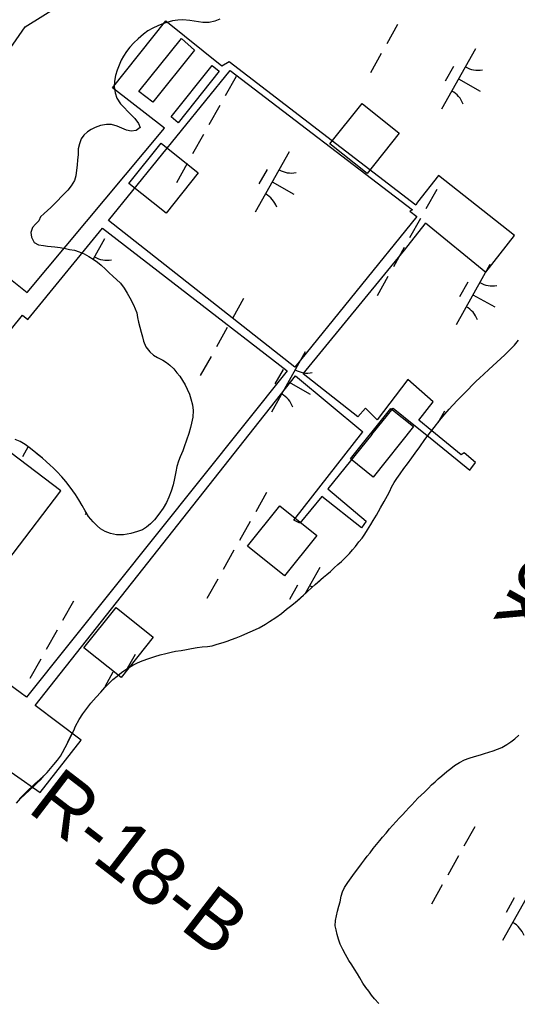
# Model space of a CAD drawing. Extents: x 3913936 to 3933962, y 195330 to 217741.
# Drawn here: x 3924387 to 3924747, y 200928 to 201638 of the extents above; entities that cross this region are included whole.
import ezdxf

# ---------------------------------------------------------------- set-up
doc = ezdxf.new("R2010")
doc.units = 0
for name, color, linetype in [('V-BLDG-IDEN', 7, 'Continuous'), ('V-BLDG-OTLN', 7, 'Continuous'), ('V-CHAN-DOCK', 7, 'Continuous'), ('V-RIVR-RANG-IDEN', 7, 'Continuous'), ('V-TOPO-SHOR', 7, 'Continuous'), ('V-UTIL-LINE', 7, 'Continuous'), ('V-WETL-SWMP', 7, 'Continuous')]:
    doc.layers.add(name, color=color, linetype=linetype)

msp = doc.modelspace()

# ---------------------------------------------------------------- linework, layer by layer
at = {"layer": 'V-BLDG-OTLN'}
for points in [[(3924611.41, 201548.37), (3924634.69, 201577.48), (3924661.53, 201556.01), (3924638.25, 201526.9)], [(3924466.2, 201519.72), (3924489.48, 201548.83), (3924516.32, 201527.36), (3924493.04, 201498.25)], [(3924626.26, 201320.71), (3924655.47, 201357.14), (3924671.75, 201344.08), (3924642.53, 201307.65)], [(3924551.86, 201257.71), (3924575.14, 201286.82), (3924601.98, 201265.35), (3924578.7, 201236.24)], [(3924433.66, 201184.32), (3924456.94, 201213.43), (3924483.78, 201191.97), (3924460.5, 201162.85)]]:
    msp.add_lwpolyline(points, close=True, dxfattribs=at)
at = {"layer": 'V-CHAN-DOCK'}
for p, q in [((3924531.46, 201600.76), (3924501.79, 201563.55)), ((3924585.29, 201276.57), (3924635.18, 201340.26)), ((3924589.71, 201274.24), (3924585.29, 201276.57))]:
    msp.add_line(p, q, dxfattribs=at)
for points in [[(3924187.34, 201603.18), (3924076.05, 201691.66), (3924082.7, 201700.08), (3924199.54, 201605.72), (3924195.57, 201600.34), (3924205.64, 201591.72), (3924259.54, 201659.81), (3924263.07, 201664.84), (3924267.32, 201661.91), (3924210.76, 201586.45), (3924392.74, 201440.95), (3924491.85, 201559.54), (3924454.38, 201588.78), (3924492.76, 201637.18), (3924533.44, 201604.75), (3924538.71, 201607.71), (3924673.37, 201504.36)], [(3924483.58, 201578.47), (3924473.43, 201586.15), (3924504.31, 201624.4), (3924513.68, 201615.94), (3924483.58, 201578.47)], [(3924674.28, 201495.97), (3924585.98, 201386.97), (3924451.45, 201493.05), (3924539.34, 201601.39)], [(3924501.79, 201563.55), (3924496.67, 201567.86), (3924526.26, 201604.81), (3924531.46, 201600.76)], [(3924539.34, 201601.39), (3924671.04, 201500.67), (3924669.19, 201499.77), (3924674.28, 201495.97)], [(3924680.49, 201491.33), (3924723.93, 201455.69), (3924744.66, 201482.18), (3924689.82, 201525.57), (3924674.65, 201506.15), (3924673.37, 201504.36)], [(3924389.28, 201424.57), (3924393.14, 201421.4), (3924447.14, 201487.32), (3924580.53, 201384.36), (3924392.31, 201148.79)], [(3924631.46, 201351.11), (3924591.96, 201382.31), (3924665.31, 201471.64), (3924680.09, 201490.61), (3924680.49, 201491.33)], [(3924356.58, 201343.42), (3924336.66, 201359.36), (3924389.28, 201424.57)], [(3924398.59, 201142.55), (3924586.43, 201380.82), (3924635.18, 201340.26)], [(3924641.75, 201338.3), (3924657.03, 201357.37), (3924673.29, 201344.32), (3924682.68, 201336.93), (3924703.27, 201320.13), (3924712.49, 201312.54), (3924716.57, 201318.26), (3924708.3, 201325.19), (3924706.13, 201323.64), (3924684.98, 201341.12), (3924675.72, 201348.81), (3924686.04, 201361.9), (3924667.79, 201378.01), (3924645.61, 201349.09), (3924637.15, 201357.38), (3924631.46, 201351.11)], [(3924392.31, 201148.79), (3924355.4, 201175.7), (3924332.26, 201147.37), (3924313.54, 201162.01), (3924416.94, 201297.65), (3924356.58, 201343.42)], [(3924641.75, 201338.3), (3924609.82, 201299.06), (3924637.6, 201275.85), (3924634.23, 201271.07), (3924605.59, 201293.6), (3924589.71, 201274.24)], [(3924354.05, 201104.83), (3924364.75, 201105.72), (3924402.07, 201079.93), (3924431.71, 201117.64), (3924398.59, 201142.55)]]:
    msp.add_lwpolyline(points, dxfattribs=at)
at = {"layer": 'V-TOPO-SHOR'}
for points in [[(3924531.95, 201638.44), (3924528.22, 201636.98), (3924524.17, 201636.03), (3924519.71, 201635.92), (3924516.59, 201636.43), (3924513.27, 201636.83), (3924510.15, 201637.34), (3924505.06, 201637.85), (3924501.43, 201637.63), (3924497.8, 201637.1), (3924494.48, 201636.16), (3924491.16, 201635.21), (3924487.01, 201633.54), (3924483.59, 201631.97), (3924479.96, 201629.99), (3924476.75, 201627.49), (3924472.81, 201624.16), (3924469.7, 201621.24), (3924466.91, 201618.22), (3924464.43, 201615)], [(3924464.43, 201615), (3924462.36, 201611.67), (3924460.71, 201608.86), (3924459.16, 201605.12), (3924457.71, 201601.48), (3924456.58, 201597.64), (3924455.76, 201593.69), (3924455.46, 201589.74), (3924456.2, 201585.08), (3924457.56, 201581.44), (3924460.07, 201577.3), (3924462.67, 201574.61), (3924465.38, 201571.81), (3924467.67, 201569.53), (3924470.48, 201566.74), (3924473.19, 201563.11), (3924474.23, 201560.21), (3924471.33, 201557.91), (3924467.81, 201557.49), (3924464.58, 201558.1), (3924461.15, 201559.76), (3924457.83, 201560.99), (3924453.67, 201562.23), (3924450.04, 201562.42), (3924445.58, 201561.48), (3924441.74, 201560.12), (3924438.83, 201558.76), (3924436.24, 201556.99), (3924433.66, 201554.7), (3924431.79, 201551.89), (3924430.56, 201548.46), (3924429.63, 201544.61), (3924429.44, 201540.36), (3924429.14, 201536.82), (3924428.84, 201532.88), (3924428.33, 201529.24), (3924427.82, 201525.3)], [(3924427.82, 201525.3), (3924426.9, 201521.97), (3924424.52, 201518.02), (3924422.03, 201514.9), (3924419.86, 201512.71), (3924417.17, 201510), (3924414.89, 201507.51), (3924412.61, 201505.21), (3924409.71, 201502.4), (3924407.33, 201500.22), (3924404.95, 201498.03), (3924402.36, 201495.53), (3924401.12, 201492.62), (3924398.64, 201490.23), (3924396.46, 201487.83), (3924395.33, 201484.4), (3924395.76, 201480.87), (3924397.74, 201477.14), (3924400.96, 201475.49), (3924404.5, 201474.88), (3924407.51, 201474.36), (3924412.6, 201473.86), (3924416.44, 201473.46), (3924420.28, 201472.84), (3924423.29, 201472.13), (3924426.83, 201471.51), (3924430.36, 201470.28), (3924433.79, 201468.94), (3924437.33, 201466.97), (3924440.34, 201465.11), (3924443.57, 201462.94), (3924446.17, 201460.67), (3924449.39, 201457.87), (3924451.79, 201455.39), (3924454.91, 201452.49), (3924457.31, 201450.42), (3924460.01, 201447.73), (3924462.72, 201444.2), (3924465.02, 201440.47), (3924466.89, 201437.05), (3924469.51, 201431.97), (3924470.66, 201429.07), (3924471.91, 201426.27), (3924472.44, 201422.95), (3924473.07, 201419.52), (3924474.12, 201415.99), (3924475.06, 201412.26), (3924475.9, 201408.83), (3924476.85, 201405.72), (3924478.31, 201401.78), (3924481.33, 201398.05), (3924483.93, 201395.78), (3924486.84, 201394.02), (3924490.69, 201392.16), (3924493.29, 201390.51), (3924495.69, 201388.54), (3924498.6, 201385.85), (3924500.79, 201383.05), (3924502.87, 201380.46), (3924504.85, 201377.46), (3924506.83, 201374.35), (3924508.4, 201371.03), (3924509.86, 201367.5), (3924511.02, 201364.19), (3924512.17, 201359.72)], [(3924703.9, 201363.48), (3924707.76, 201367.26), (3924711.22, 201370.94), (3924714.26, 201374.11), (3924717.01, 201376.87), (3924719.45, 201379.12), (3924722.5, 201381.98), (3924726.25, 201385.25), (3924729, 201388.01), (3924731.95, 201390.66), (3924734.89, 201393.32), (3924737.84, 201395.88), (3924739.98, 201398.12), (3924742.41, 201400.58), (3924744.65, 201402.93), (3924747.59, 201406.5)], [(3924512.17, 201359.72), (3924512.7, 201355.78), (3924512.4, 201350.9), (3924511.48, 201346.64), (3924510.76, 201343.42), (3924509.53, 201339.16), (3924507.88, 201334.38), (3924506.23, 201329.39), (3924505.1, 201326.58), (3924503.24, 201322.22), (3924502, 201319.1), (3924500.87, 201315.36), (3924500.05, 201311.41), (3924499.13, 201306.74), (3924498.11, 201302.06), (3924496.67, 201297.49), (3924495.12, 201293.02), (3924493.37, 201289.28), (3924490.99, 201285.22), (3924487.78, 201280.75), (3924484.68, 201276.69), (3924481.89, 201273.78), (3924478.99, 201271.38), (3924476.08, 201269.61), (3924472.35, 201268.25), (3924467.58, 201266.88), (3924462.39, 201265.93), (3924457.3, 201265.92), (3924452.83, 201266.84), (3924448.99, 201268.29), (3924445.76, 201270.36), (3924443.27, 201272.42), (3924440.35, 201275.32), (3924437.12, 201279.26), (3924434.62, 201283.2), (3924432.32, 201287.03), (3924429.93, 201291.18)], [(3924511.32, 201183.83), (3924515.39, 201184.45), (3924519.16, 201184.97), (3924523.03, 201185.39), (3924526.29, 201185.7), (3924530.06, 201186.93), (3924534.33, 201188.17), (3924537.19, 201189.19), (3924540.24, 201190.22), (3924543.7, 201191.56), (3924547.36, 201193.1), (3924552.04, 201195.04), (3924555.4, 201196.58), (3924560.19, 201198.73), (3924564.87, 201201.4), (3924567.71, 201203.24), (3924572.29, 201206.31), (3924576.36, 201209.17), (3924580.02, 201212.14), (3924582.86, 201214.39), (3924586.32, 201217.15), (3924589.37, 201219.81), (3924592.42, 201222.46), (3924595.26, 201224.92), (3924598.31, 201227.88), (3924600.85, 201230.02), (3924603.8, 201232.68), (3924606.75, 201235.34), (3924609.19, 201237.39), (3924611.83, 201239.53), (3924614.58, 201242.09), (3924617.22, 201244.44), (3924619.76, 201246.69), (3924623.11, 201250.16), (3924625.45, 201252.51), (3924627.79, 201255.17), (3924629.82, 201257.62), (3924632.35, 201260.78), (3924634.59, 201263.54), (3924636.62, 201266.5), (3924638.55, 201269.66), (3924640.88, 201273.34), (3924642.71, 201276.2), (3924645.04, 201280.18), (3924647.98, 201285.38), (3924650.61, 201290.08), (3924652.95, 201294.26), (3924654.77, 201297.42), (3924655.98, 201300.38), (3924657.81, 201303.75), (3924659.64, 201306.51), (3924662.17, 201310.08), (3924664.91, 201313.75), (3924667.55, 201317.33), (3924670.6, 201321.62), (3924673.03, 201324.99), (3924676.28, 201329.58), (3924680.04, 201334.79), (3924682.47, 201337.95), (3924686.74, 201343.57), (3924690.9, 201348.77), (3924694.45, 201353.17), (3924697.6, 201356.74), (3924700.04, 201359.4), (3924703.9, 201363.48)], [(3924429.93, 201291.18), (3924427.53, 201295.12), (3924425.65, 201297.81), (3924423.15, 201301.23), (3924420.54, 201304.44), (3924417.73, 201307.76), (3924414.09, 201311.59), (3924411.59, 201314.28), (3924409.3, 201316.35), (3924406.49, 201318.83), (3924403.89, 201321.21), (3924400.76, 201323.8), (3924397.64, 201326.39), (3924394.21, 201329.08), (3924391.29, 201331.25), (3924387.66, 201333.32), (3924384.12, 201334.76)], [(3924404.7, 201091.83), (3924407.13, 201094.38), (3924409.67, 201097.14), (3924412.01, 201100), (3924414.55, 201103.16), (3924416.68, 201106.12), (3924418.3, 201108.78), (3924420.23, 201112.45), (3924422.05, 201116.12), (3924424.08, 201120.21), (3924426.31, 201124.7), (3924427.72, 201127.65), (3924430.36, 201132.55), (3924432.89, 201136.64), (3924435.13, 201139.49), (3924438.78, 201144.29), (3924442.54, 201148.58), (3924445.89, 201152.36), (3924448.84, 201155.63), (3924451.58, 201158.39), (3924454.63, 201161.35), (3924457.68, 201163.91), (3924460.83, 201166.46), (3924463.27, 201168.3), (3924465.81, 201169.94), (3924468.97, 201171.78), (3924472.43, 201173.43), (3924475.89, 201174.86), (3924480.57, 201176.71), (3924484.84, 201178.15), (3924488.81, 201179.38), (3924492.79, 201180.31), (3924496.66, 201181.13), (3924499.91, 201181.86), (3924503.89, 201182.48), (3924507.75, 201183.2), (3924511.32, 201183.83)], [(3924715.83, 201105.81), (3924720.1, 201106.99), (3924723.08, 201107.9), (3924726.18, 201108.95), (3924729.29, 201109.86), (3924732.52, 201111.04), (3924735.62, 201112.34), (3924739.24, 201114.42), (3924742.09, 201116.5), (3924744.93, 201118.71), (3924747.77, 201121.31)], [(3924646.71, 200927.43), (3924643.64, 200930.82), (3924641.54, 200933.45), (3924639.43, 200936.27), (3924637.36, 200939.06), (3924635.27, 200942.13), (3924633.04, 200945.93), (3924631.22, 200948.88), (3924629.24, 200952.26), (3924627.31, 200955.29), (3924625.05, 200958.6), (3924622.69, 200962.81), (3924620.71, 200966.53), (3924618.91, 200970.39), (3924617.69, 200973.83), (3924616.72, 200977.21), (3924615.83, 200980.55), (3924615.2, 200983.5), (3924615.42, 200987.44), (3924616.06, 200990.65), (3924616.95, 200994.18), (3924617.85, 200997.67), (3924618.72, 201000.96), (3924619.62, 201004.95), (3924620.38, 201008.06), (3924621.93, 201011.3), (3924624.25, 201014.93), (3924626.7, 201018.31), (3924629.15, 201021.68), (3924631.47, 201024.66), (3924634.31, 201028.3), (3924636.5, 201031.28), (3924638.31, 201033.74), (3924640.5, 201036.34), (3924642.7, 201039.33), (3924645.02, 201042.18), (3924647.34, 201045.04), (3924649.4, 201047.5), (3924651.98, 201050.49), (3924654.49, 201053.47), (3924656.68, 201056.06), (3924659.26, 201058.79), (3924661.46, 201061.26), (3924663.78, 201063.59), (3924666.23, 201066.45), (3924668.43, 201068.78), (3924670.49, 201070.99), (3924672.81, 201073.33), (3924675.01, 201075.8), (3924677.33, 201078), (3924679.66, 201080.08), (3924682.5, 201082.94), (3924684.82, 201085.27), (3924687.41, 201087.61), (3924689.6, 201089.69), (3924692.18, 201091.9), (3924695.93, 201095.01), (3924698.64, 201097.09), (3924701.48, 201099.3), (3924704.97, 201101.51), (3924708.59, 201103.33), (3924712.08, 201104.64), (3924715.83, 201105.81)], [(3924387.11, 201075.27), (3924390.26, 201078.34), (3924393.52, 201081.4), (3924396.36, 201084.06), (3924398.6, 201086.21), (3924401.85, 201089.17), (3924404.7, 201091.83)]]:
    msp.add_lwpolyline(points, dxfattribs=at)
at = {"layer": 'V-UTIL-LINE'}
msp.add_lwpolyline([(3922259.35, 198607.65), (3922481.8, 198996.51), (3922891.23, 199568.37), (3923401.91, 200205.88), (3924391.34, 201632.88), (3925141.51, 202100.49), (3925635.89, 202689.84), (3926060.57, 203224.55), (3926266.36, 203722.12), (3926398.76, 204373.14), (3926759.45, 205211.96), (3927229.53, 206070.79), (3927602.51, 206766.2), (3928031.78, 207586.17)], dxfattribs=at)
at = {"layer": 'V-WETL-SWMP'}
for p, q in [((3924660.26, 201634.53), (3924652.42, 201620.58)), ((3924716.6, 201616.97), (3924692.1, 201573.38)), ((3924648.5, 201613.61), (3924640.66, 201599.66)), ((3924700.56, 201604.19), (3924694.68, 201593.72)), ((3924543.59, 201596.87), (3924535.75, 201582.92)), ((3924704.35, 201595.17), (3924720.04, 201586.35)), ((3924531.83, 201575.95), (3924523.99, 201562)), ((3924520.07, 201555.03), (3924512.23, 201541.08)), ((3924582, 201542.68), (3924557.5, 201499.09)), ((3924508.31, 201534.11), (3924500.47, 201520.16)), ((3924565.96, 201529.9), (3924560.08, 201519.43)), ((3924569.75, 201520.88), (3924585.44, 201512.06)), ((3924688.59, 201515.36), (3924680.75, 201501.41)), ((3924676.83, 201494.44), (3924668.99, 201480.49)), ((3924448.63, 201479.72), (3924440.4, 201465.08)), ((3924665.07, 201473.52), (3924657.23, 201459.57)), ((3924726.99, 201461.17), (3924702.49, 201417.58)), ((3924653.31, 201452.6), (3924645.47, 201438.65)), ((3924710.96, 201448.39), (3924705.08, 201437.93)), ((3924714.74, 201439.37), (3924730.43, 201430.55)), ((3924549.05, 201436.69), (3924541.21, 201422.75)), ((3924537.29, 201415.77), (3924529.45, 201401.82)), ((3924525.53, 201394.85), (3924517.69, 201380.9)), ((3924593.63, 201398.21), (3924569.13, 201354.62)), ((3924577.59, 201385.43), (3924571.71, 201374.97)), ((3924581.38, 201376.42), (3924597.07, 201367.59)), ((3924694.05, 201355.18), (3924689.37, 201346.86)), ((3924393.39, 201329.68), (3924389.26, 201322.32)), ((3924565.62, 201296.6), (3924557.77, 201282.66)), ((3924435.42, 201281.93), (3924434.52, 201280.33)), ((3924553.85, 201275.68), (3924546.01, 201261.73)), ((3924542.09, 201254.76), (3924534.25, 201240.81)), ((3924604.02, 201242.41), (3924593.18, 201223.12)), ((3924530.33, 201233.84), (3924522.49, 201219.89)), ((3924587.99, 201229.63), (3924582.1, 201219.17)), ((3924426.08, 201217.93), (3924418.24, 201203.99)), ((3924414.32, 201197.01), (3924406.48, 201183.07)), ((3924402.56, 201176.09), (3924394.72, 201162.14)), ((3924470.65, 201179.45), (3924465.02, 201169.43)), ((3924454.62, 201166.67), (3924448.74, 201156.21)), ((3924716.07, 201054.92), (3924708.23, 201040.97)), ((3924704.31, 201033.99), (3924696.47, 201020.05)), ((3924692.55, 201013.07), (3924684.71, 200999.13)), ((3924760.65, 201016.43), (3924736.15, 200972.85)), ((3924744.61, 201003.65), (3924738.73, 200993.19))]:
    msp.add_line(p, q, dxfattribs=at)
for points in [[(3924531.95, 201638.44), (3924528.22, 201636.98), (3924524.17, 201636.03), (3924519.71, 201635.92), (3924516.59, 201636.43), (3924513.27, 201636.83), (3924510.15, 201637.34), (3924505.06, 201637.85), (3924501.43, 201637.63), (3924497.8, 201637.1), (3924491.16, 201635.21), (3924487.01, 201633.54), (3924483.59, 201631.98), (3924479.96, 201629.99), (3924476.75, 201627.49), (3924472.81, 201624.16), (3924469.7, 201621.24), (3924466.91, 201618.22), (3924464.43, 201615), (3924462.36, 201611.67), (3924460.71, 201608.86), (3924459.16, 201605.12), (3924457.71, 201601.48), (3924456.58, 201597.64), (3924455.76, 201593.69), (3924455.46, 201589.74), (3924456.2, 201585.07), (3924457.56, 201581.44), (3924460.07, 201577.3), (3924462.67, 201574.61), (3924465.38, 201571.81), (3924470.48, 201566.74), (3924473.19, 201563.11), (3924474.23, 201560.21), (3924471.33, 201557.91), (3924467.81, 201557.49), (3924464.58, 201558.1), (3924461.15, 201559.76), (3924457.83, 201560.99), (3924453.67, 201562.23), (3924450.04, 201562.42), (3924445.58, 201561.48), (3924441.74, 201560.12), (3924438.83, 201558.76), (3924436.24, 201556.99), (3924433.66, 201554.69), (3924431.79, 201551.89), (3924430.56, 201548.46), (3924429.63, 201544.61), (3924429.44, 201540.36), (3924429.14, 201536.82), (3924428.84, 201532.88), (3924428.33, 201529.24), (3924427.82, 201525.3), (3924426.89, 201521.97), (3924424.52, 201518.02), (3924422.03, 201514.9), (3924417.17, 201510), (3924414.89, 201507.51), (3924412.61, 201505.21), (3924409.71, 201502.4), (3924404.95, 201498.03), (3924402.36, 201495.53), (3924401.12, 201492.62), (3924398.64, 201490.23), (3924396.46, 201487.83), (3924395.33, 201484.4), (3924395.76, 201480.87), (3924397.74, 201477.14), (3924400.96, 201475.49), (3924404.5, 201474.88), (3924407.51, 201474.36), (3924412.6, 201473.86), (3924416.44, 201473.46), (3924420.28, 201472.84), (3924423.29, 201472.12), (3924426.83, 201471.51), (3924430.36, 201470.28), (3924433.79, 201468.94), (3924437.33, 201466.97), (3924440.34, 201465.11), (3924443.57, 201462.94), (3924446.17, 201460.66), (3924449.39, 201457.87), (3924451.79, 201455.39), (3924454.91, 201452.49), (3924457.31, 201450.42), (3924460.01, 201447.73), (3924462.72, 201444.2), (3924465.02, 201440.47), (3924466.9, 201437.05), (3924469.5, 201431.97), (3924470.66, 201429.07), (3924471.91, 201426.27), (3924472.44, 201422.95), (3924473.07, 201419.52), (3924474.12, 201415.99), (3924475.06, 201412.26), (3924475.9, 201408.83)], [(3924475.9, 201408.83), (3924476.85, 201405.72), (3924478.31, 201401.78), (3924481.33, 201398.05), (3924483.93, 201395.78), (3924486.85, 201394.02), (3924490.69, 201392.16), (3924493.29, 201390.51), (3924495.69, 201388.54), (3924498.6, 201385.85), (3924500.79, 201383.05), (3924502.87, 201380.46), (3924504.85, 201377.46), (3924506.83, 201374.35), (3924508.4, 201371.03), (3924509.86, 201367.5), (3924511.02, 201364.18), (3924512.17, 201359.72), (3924512.7, 201355.78), (3924512.4, 201350.9), (3924511.48, 201346.64), (3924510.76, 201343.42), (3924509.53, 201339.16), (3924507.88, 201334.38), (3924506.23, 201329.39), (3924505.1, 201326.58), (3924503.24, 201322.22), (3924502, 201319.1), (3924500.87, 201315.36), (3924500.05, 201311.41), (3924499.13, 201306.74), (3924498.11, 201302.06), (3924496.67, 201297.49), (3924495.12, 201293.02), (3924493.37, 201289.28), (3924490.99, 201285.22), (3924487.78, 201280.75), (3924484.68, 201276.69), (3924481.89, 201273.78), (3924478.98, 201271.38), (3924476.08, 201269.61), (3924472.35, 201268.25), (3924467.58, 201266.88), (3924462.39, 201265.93), (3924457.3, 201265.92), (3924452.83, 201266.84), (3924448.99, 201268.29), (3924445.76, 201270.35), (3924443.27, 201272.42), (3924440.35, 201275.32), (3924437.12, 201279.26), (3924434.62, 201283.2), (3924432.32, 201287.03), (3924429.93, 201291.18), (3924427.53, 201295.12), (3924425.65, 201297.81), (3924423.15, 201301.23), (3924420.54, 201304.44), (3924417.73, 201307.76), (3924414.09, 201311.59), (3924411.59, 201314.28), (3924409.3, 201316.35), (3924406.49, 201318.83), (3924403.89, 201321.21), (3924397.64, 201326.39), (3924394.21, 201329.08), (3924391.29, 201331.25), (3924387.66, 201333.32), (3924384.12, 201334.76)], [(3924507.75, 201183.2), (3924511.32, 201183.82), (3924515.39, 201184.45), (3924519.16, 201184.97), (3924523.03, 201185.39), (3924526.29, 201185.7), (3924530.06, 201186.93), (3924534.33, 201188.17), (3924537.19, 201189.19), (3924540.24, 201190.22), (3924543.7, 201191.56), (3924547.36, 201193.1), (3924552.04, 201195.04), (3924555.4, 201196.58), (3924560.19, 201198.73), (3924564.87, 201201.4), (3924567.71, 201203.24), (3924572.29, 201206.31), (3924576.36, 201209.17), (3924580.02, 201212.14), (3924582.86, 201214.39), (3924586.32, 201217.15), (3924592.42, 201222.46), (3924595.26, 201224.92), (3924598.31, 201227.88), (3924600.85, 201230.03), (3924606.75, 201235.34), (3924609.19, 201237.39), (3924611.83, 201239.53), (3924614.58, 201242.09), (3924617.22, 201244.44), (3924619.76, 201246.69), (3924623.11, 201250.16), (3924625.45, 201252.51), (3924627.79, 201255.17), (3924629.82, 201257.62), (3924632.35, 201260.78), (3924634.59, 201263.54), (3924636.62, 201266.5), (3924638.54, 201269.66), (3924640.88, 201273.34), (3924642.7, 201276.2), (3924645.04, 201280.18), (3924647.98, 201285.38), (3924650.61, 201290.08), (3924652.95, 201294.26), (3924654.77, 201297.42), (3924655.98, 201300.38), (3924657.81, 201303.75), (3924659.64, 201306.51), (3924662.17, 201310.08), (3924664.91, 201313.75), (3924667.55, 201317.33), (3924670.6, 201321.62), (3924673.03, 201324.99), (3924676.28, 201329.58), (3924680.04, 201334.79), (3924682.47, 201337.95), (3924686.74, 201343.57), (3924690.9, 201348.77), (3924694.45, 201353.17), (3924697.6, 201356.74), (3924700.04, 201359.4), (3924703.9, 201363.48), (3924707.76, 201367.26), (3924711.22, 201370.94), (3924714.26, 201374.11), (3924717.01, 201376.87), (3924719.45, 201379.12), (3924722.5, 201381.98), (3924726.25, 201385.25), (3924729, 201388.01), (3924734.89, 201393.32), (3924737.84, 201395.88), (3924739.98, 201398.12), (3924742.41, 201400.58), (3924744.65, 201402.93), (3924747.59, 201406.5)], [(3924385.1, 201072.24), (3924387.95, 201075.41), (3924391.1, 201078.47), (3924394.35, 201081.54), (3924397.19, 201084.2), (3924399.43, 201086.34), (3924402.68, 201089.31), (3924404.69, 201091.83), (3924407.13, 201094.38), (3924409.67, 201097.14), (3924412.01, 201100), (3924414.54, 201103.16), (3924416.68, 201106.12), (3924418.3, 201108.78), (3924420.23, 201112.45), (3924426.31, 201124.7), (3924427.72, 201127.65), (3924430.36, 201132.55), (3924432.89, 201136.63), (3924435.13, 201139.49), (3924438.78, 201144.29), (3924442.54, 201148.58), (3924445.89, 201152.36), (3924448.84, 201155.63), (3924451.58, 201158.39), (3924454.63, 201161.35), (3924457.68, 201163.91), (3924460.83, 201166.46), (3924463.27, 201168.3), (3924465.81, 201169.94), (3924468.97, 201171.79), (3924472.43, 201173.43), (3924475.89, 201174.86), (3924480.57, 201176.71), (3924484.84, 201178.15), (3924488.81, 201179.38), (3924492.79, 201180.31), (3924496.66, 201181.13), (3924499.91, 201181.86), (3924503.89, 201182.48), (3924507.75, 201183.2)], [(3924742.09, 201116.5), (3924744.93, 201118.71), (3924747.77, 201121.31)], [(3924646.71, 200927.43), (3924643.64, 200930.81), (3924641.54, 200933.45), (3924639.43, 200936.27), (3924637.35, 200939.06), (3924635.27, 200942.13), (3924633.04, 200945.93), (3924631.22, 200948.88), (3924629.24, 200952.26), (3924627.31, 200955.29), (3924625.05, 200958.6), (3924622.69, 200962.81), (3924620.71, 200966.53), (3924618.91, 200970.39), (3924617.68, 200973.83), (3924616.72, 200977.21), (3924615.83, 200980.55), (3924615.2, 200983.5), (3924615.42, 200987.44), (3924616.06, 200990.65), (3924616.95, 200994.18), (3924617.85, 200997.67), (3924618.72, 201000.96), (3924619.62, 201004.95), (3924620.38, 201008.06), (3924621.93, 201011.3), (3924624.25, 201014.93), (3924626.7, 201018.31), (3924629.15, 201021.68), (3924631.47, 201024.67), (3924634.31, 201028.3), (3924636.5, 201031.28), (3924638.31, 201033.75), (3924640.5, 201036.34), (3924642.69, 201039.33), (3924645.02, 201042.18), (3924647.34, 201045.04), (3924649.4, 201047.5), (3924651.98, 201050.49), (3924654.49, 201053.47), (3924656.68, 201056.07), (3924659.26, 201058.79), (3924661.46, 201061.26), (3924663.78, 201063.59), (3924666.23, 201066.45), (3924668.43, 201068.79), (3924670.49, 201070.99), (3924672.81, 201073.33), (3924675.01, 201075.79), (3924677.33, 201078), (3924679.66, 201080.08), (3924682.5, 201082.93), (3924684.82, 201085.27), (3924687.4, 201087.61), (3924689.6, 201089.69), (3924692.18, 201091.9), (3924695.93, 201095.01), (3924698.64, 201097.09), (3924701.48, 201099.3), (3924704.97, 201101.51), (3924708.59, 201103.33), (3924712.08, 201104.64), (3924715.83, 201105.81), (3924720.1, 201106.99), (3924723.08, 201107.9), (3924726.18, 201108.95), (3924729.29, 201109.86), (3924732.52, 201111.04), (3924735.62, 201112.34), (3924739.24, 201114.42), (3924742.09, 201116.5)]]:
    msp.add_lwpolyline(points, dxfattribs=at)
for centre, start, end in [((3924718.09, 201619.14), 239.88608, 281.42974), ((3924691.02, 201570.98), 19.88608, 61.42973), ((3924583.49, 201544.85), 239.88608, 281.42974), ((3924556.42, 201496.69), 19.88608, 61.42973), ((3924450.12, 201481.89), 239.88608, 281.42974), ((3924728.49, 201463.34), 239.88608, 281.42974), ((3924701.42, 201415.18), 19.88608, 61.42973), ((3924595.12, 201400.38), 239.88608, 281.42974), ((3924568.05, 201352.22), 19.88608, 61.42973), ((3924605.51, 201244.58), 239.88608, 247.58896), ((3924735.07, 200970.44), 19.88608, 61.42973)]:
    msp.add_arc(centre, 17.62, start, end, dxfattribs=at)

# ---------------------------------------------------------------- texts
at = {"layer": 'V-BLDG-IDEN'}
msp.add_text('Loading Dock', height=41.9999, rotation=240.65788, dxfattribs=at).set_placement((3924897.79, 201504.64))
at = {"layer": 'V-RIVR-RANG-IDEN'}
msp.add_text('R-18-B', height=41.5, rotation=322.4335, dxfattribs=at).set_placement((3924392.01, 201066.7))

doc.saveas('drawing.dxf')
